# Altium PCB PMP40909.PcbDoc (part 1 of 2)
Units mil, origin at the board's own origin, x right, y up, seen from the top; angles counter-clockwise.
Board outline 3960.53 x 2185.03 mil, 4 copper layers (Top Layer, Signal Layer 1, Signal Layer 2, Bottom Layer), stack 45.434 mil thick; 68 components, 27 nets, 148 pads, 352 vias.
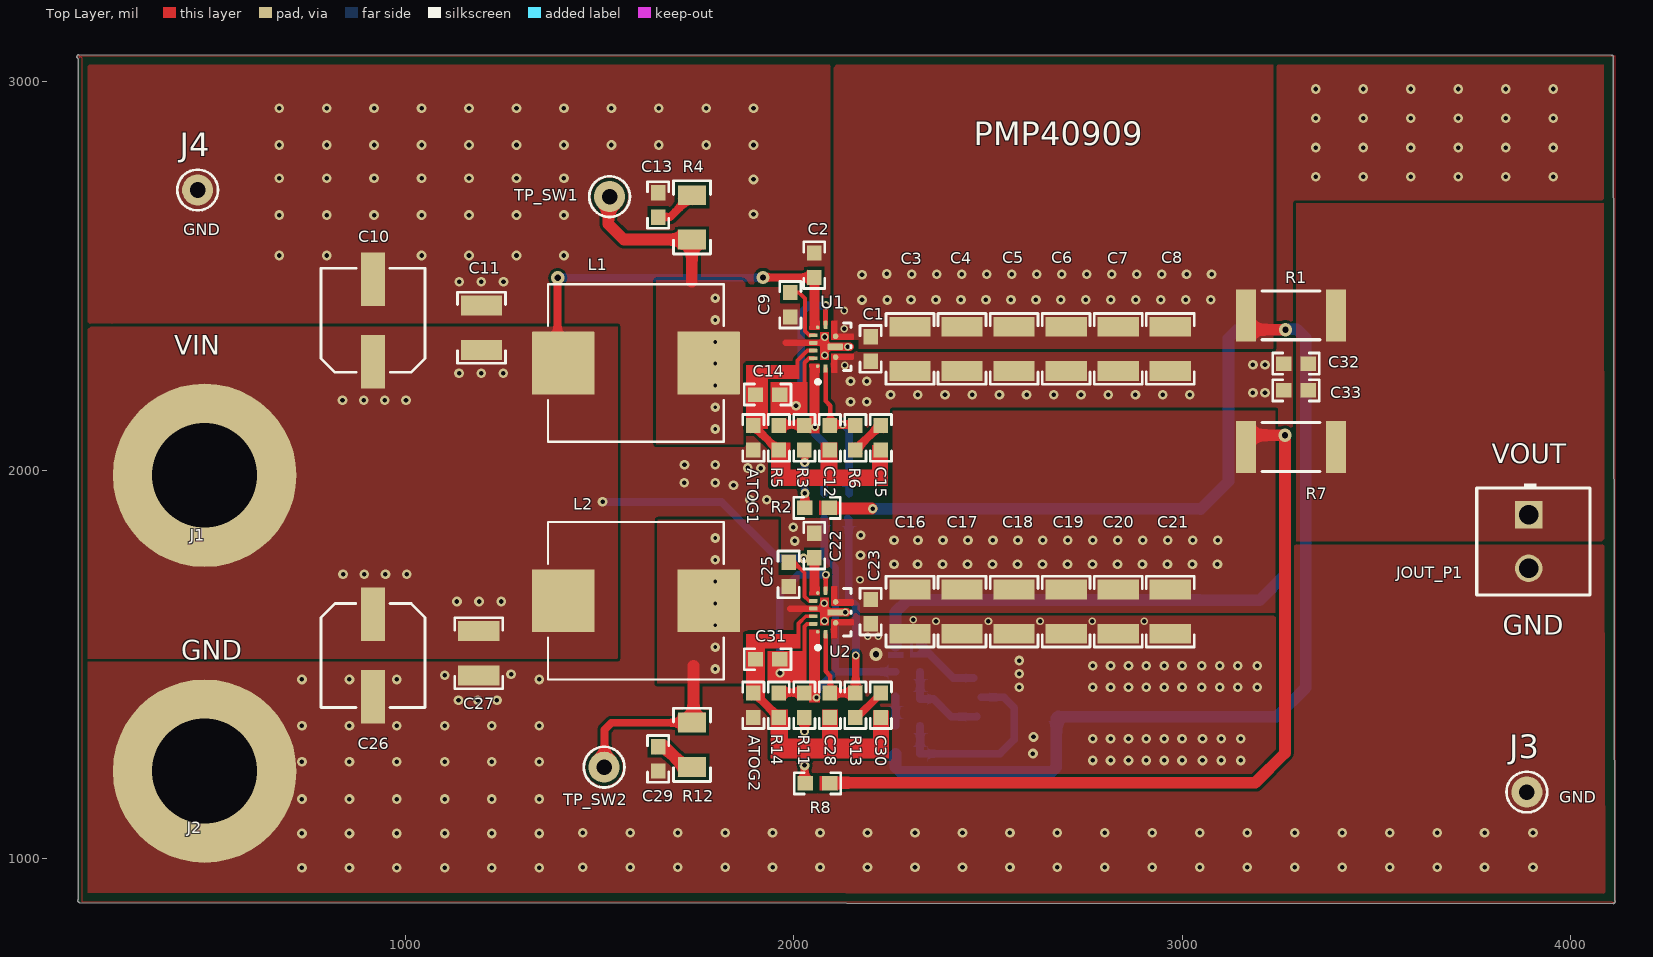
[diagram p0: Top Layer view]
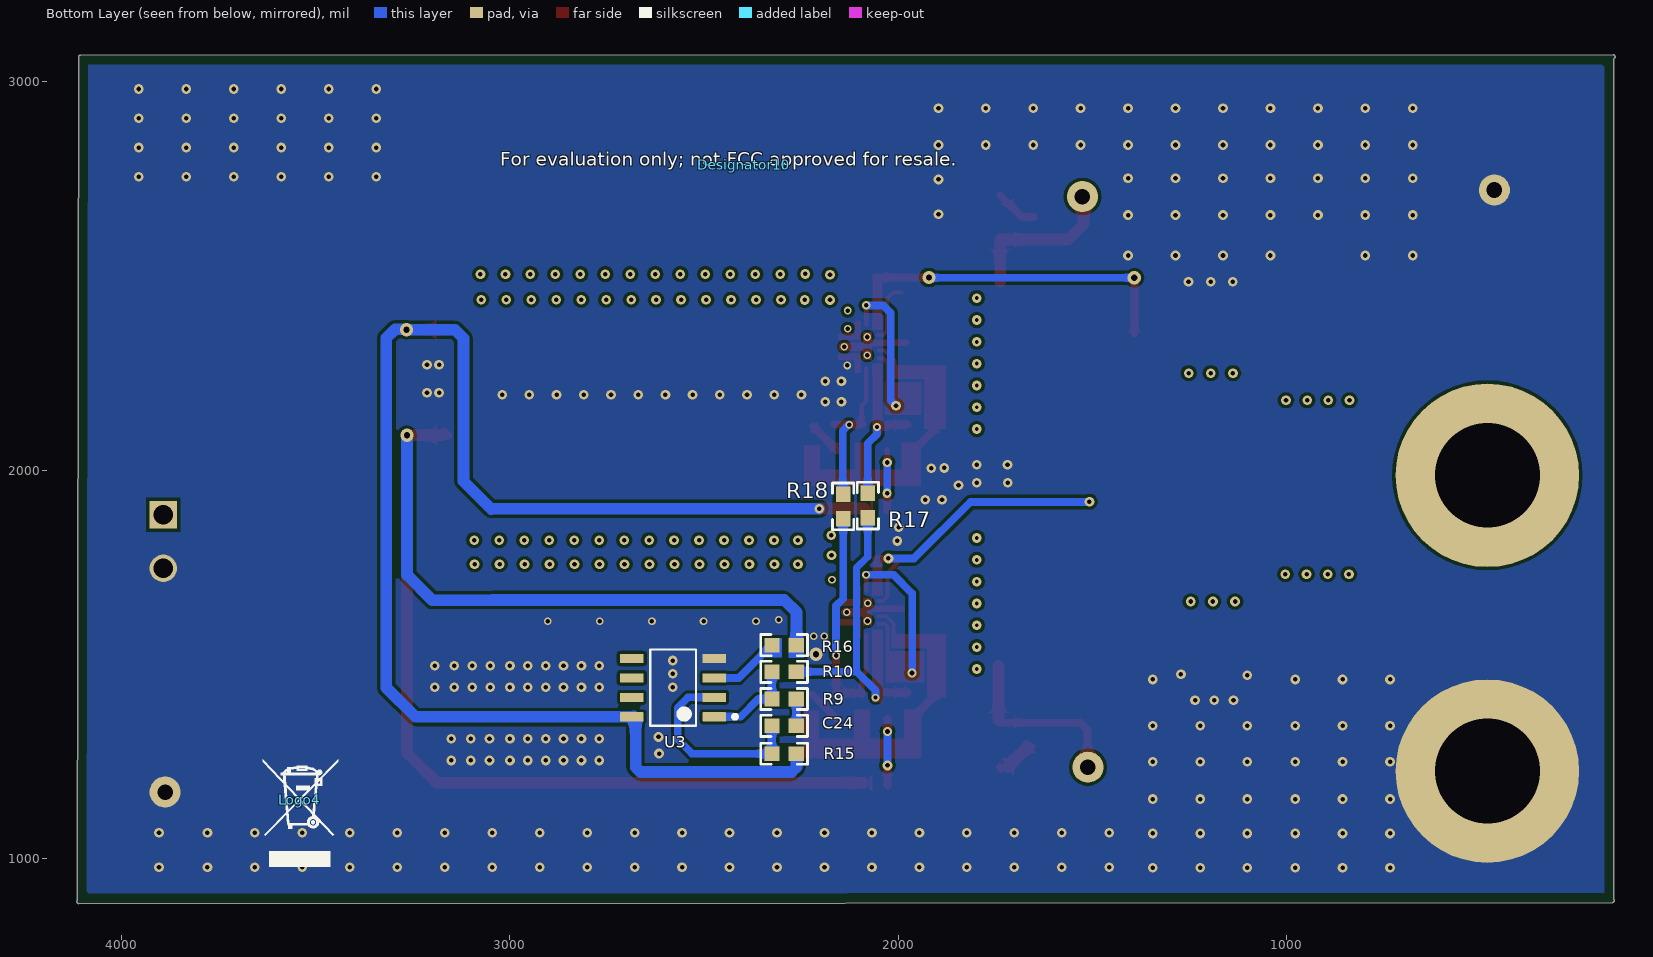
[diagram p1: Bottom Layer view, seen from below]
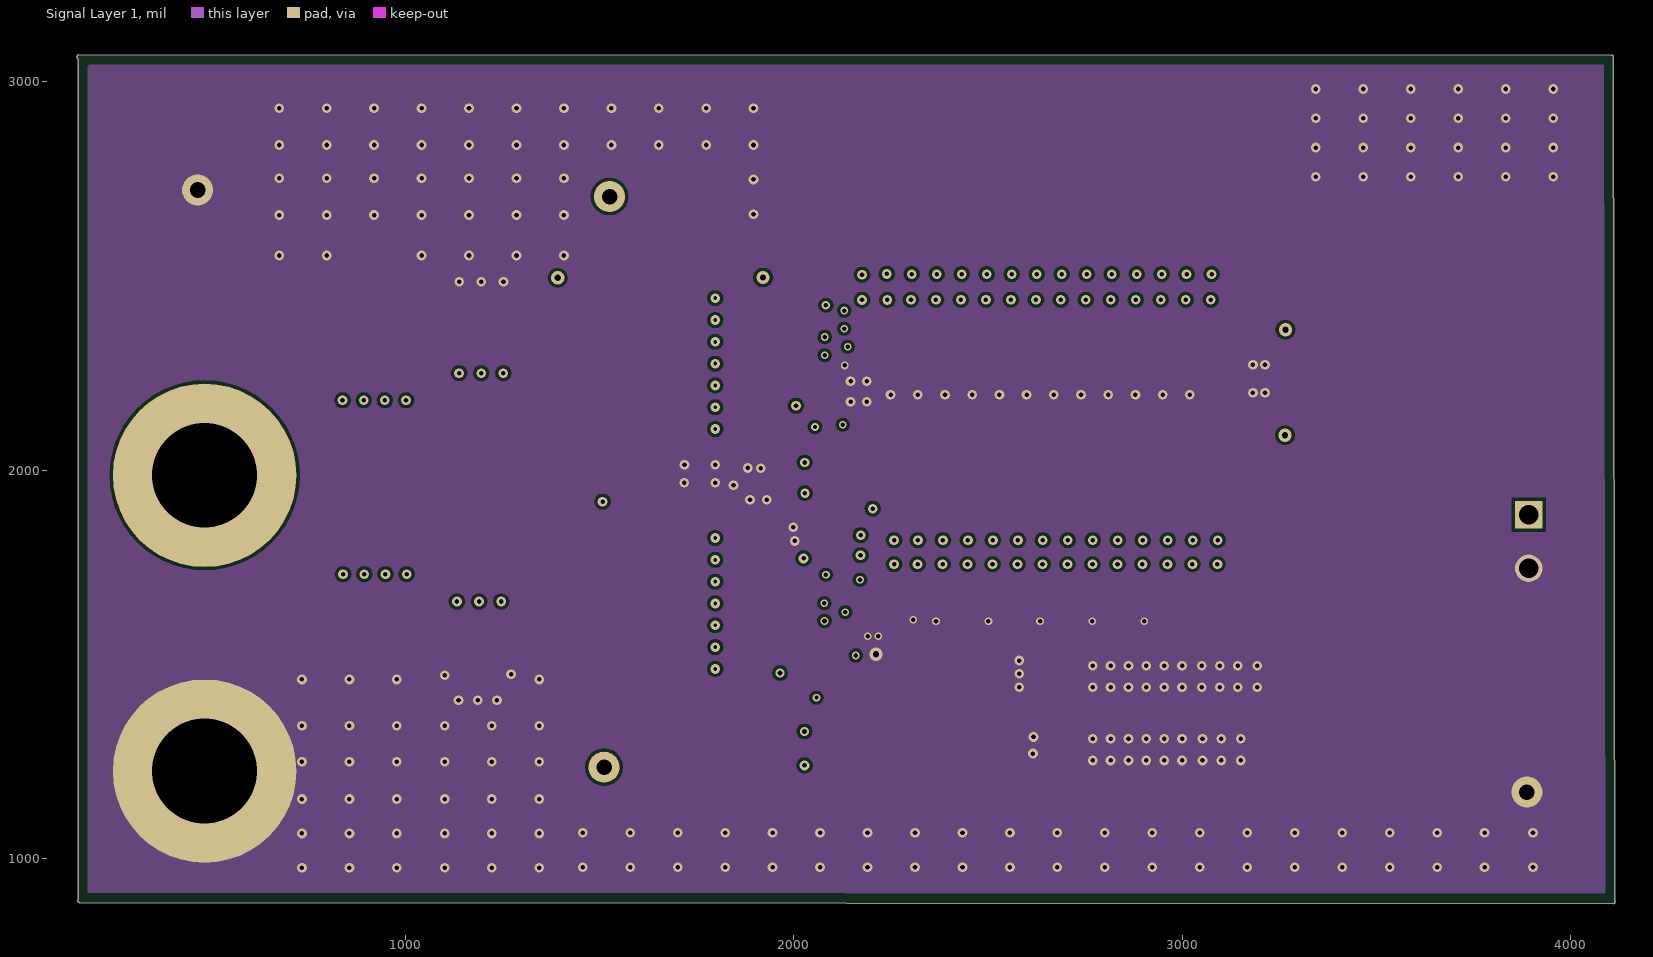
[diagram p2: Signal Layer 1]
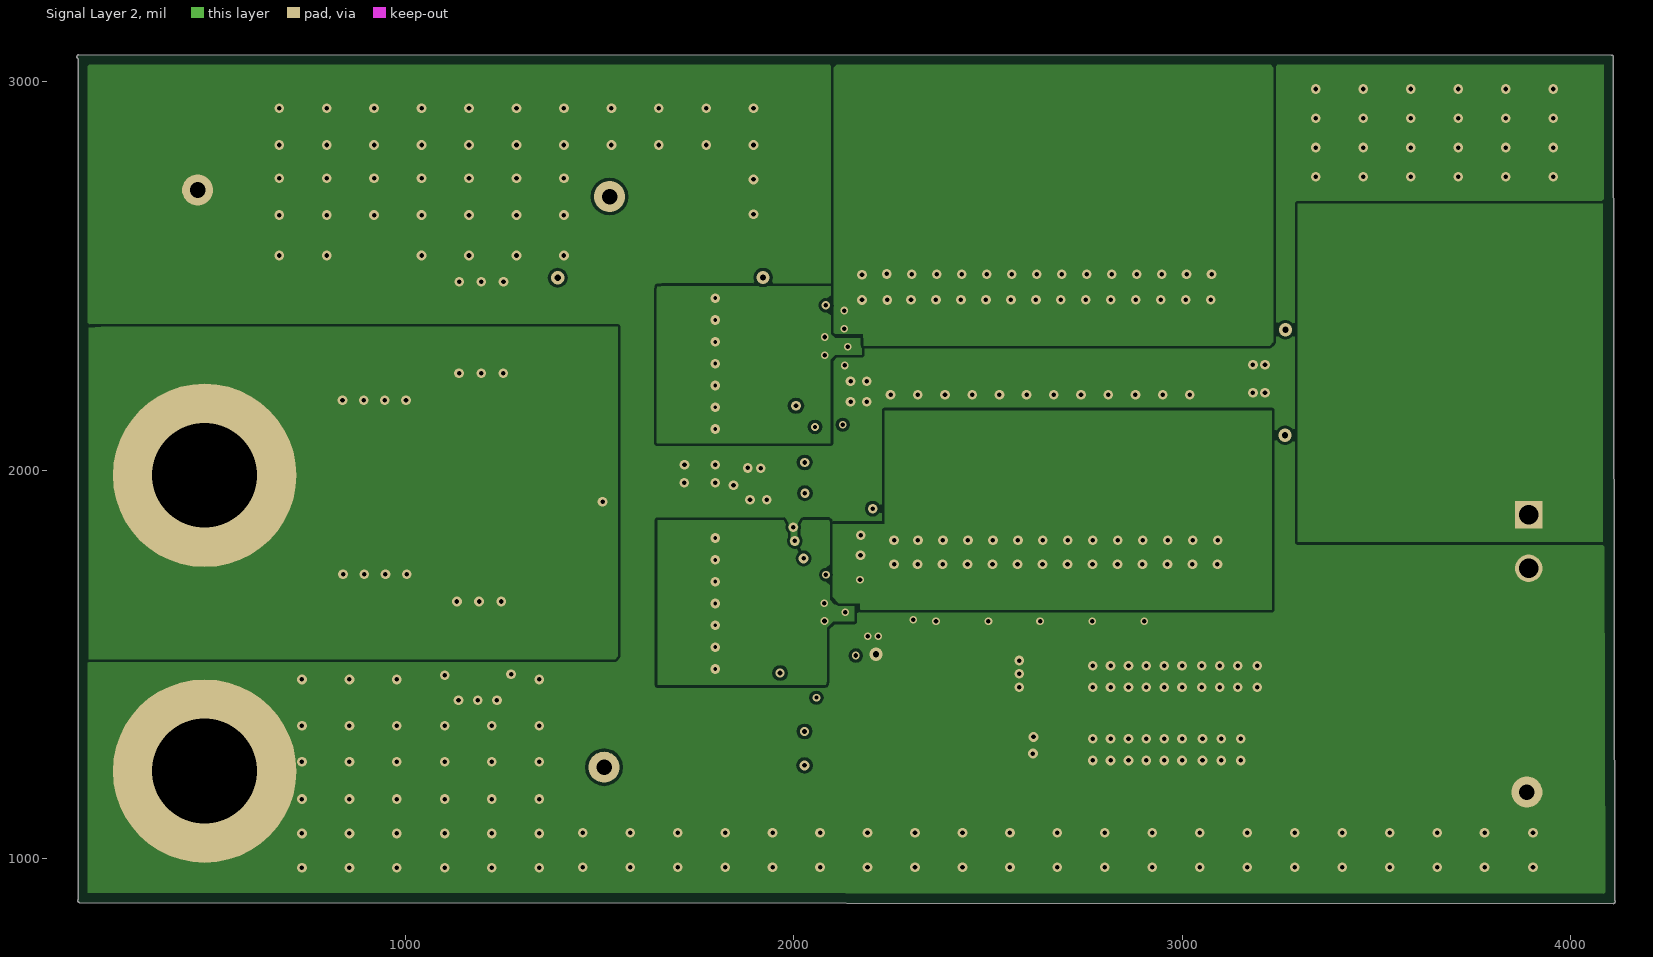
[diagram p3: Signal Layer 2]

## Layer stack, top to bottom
Top Solder: solder mask 0.4, Solder Resist, Dk 3.5
Top Layer: signal copper 2.8
Dielectric1: core 13, FR-4, Dk 4.8
Signal Layer 1: signal copper 1.417
Dielectric 2: core 11, FR-4, Dk 4.2
Signal Layer 2: signal copper 1.417
Dielectric 3: core 13, FR-4, Dk 4.2
Bottom Layer: signal copper 2.8
Bottom Solder: solder mask 0.4, Solder Resist, Dk 3.5

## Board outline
157.49,897 157.49,3059 cw(c162.5,3059) 157.56,3059.87 cw(c159.5,3064.5) 159.5,3069.52 4105.5,3069.02 cw(c4105.5,3064) 4110.52,3064 cw(c4105.5,3064) 4110.51,3063.75 cw(c4105.5,3063.5) 4110.52,3063.51 4114.34,892.02 cw(c4110,889.5) 4115.02,889.5 cw(c4110,889.5) 4110,884.49 162,886.99 cw(c162,892) 157.93,894.93 cw(c162.5,897)

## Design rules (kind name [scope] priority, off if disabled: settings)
AcuteAngle [All] p1: minimum=4.50000000000000E+0001 checktracksonly=FALSE
AssemblyTestPointUsage [All] p1: valid=2
BoardOutlineClearance BoardOutlineClearance_MountingHoles [OnCopper and InComponentClass('Mounting Holes')] p1: gap=39.37 ignorepadtopadclearanceinfootprint=FALSE
BoardOutlineClearance BoardOutlineClearance_Poly [OnCopper and IsPoly] p2: gap=25 ignorepadtopadclearanceinfootprint=FALSE
BoardOutlineClearance [OnCopper and Not InComponentClass('Logo') and not InComponentClass('FiducialMark') and not InRegion(1000,500,4000,800) and not InPoly] p3: gap=75 ignorepadtopadclearanceinfootprint=FALSE
Clearance Clearance_Keepouts [((IsTrack Or IsArc) And Not InPoly) And IsFree and IsKeepOut vs ((IsTrack Or IsArc) And Not InPoly) And IsFree and IsKeepOut] p1: gap=0 ignorepadtopadclearanceinfootprint=FALSE
Clearance Clearance_Poly [InPolygon] p2: gap=8 ignorepadtopadclearanceinfootprint=TRUE
Clearance Clearance_FiducialMark [IsKeepOut and InComponentClass('FiducialMark') vs IsPad and InComponentClass('FiducialMark')] p3: gap=0 ignorepadtopadclearanceinfootprint=FALSE
Clearance [All] p4: gap=6 ignorepadtopadclearanceinfootprint=TRUE
ComponentClearance ComponentClearance_MountingHoles_FiducialMarks [InComponentClass('Mounting Holes') vs InComponentClass('FiducialMark')] p1: gap=50 collisioncheckmode=3 verticalgap=10 showdistances=FALSE
ComponentClearance ComponentClearance_Shunt [InComponentClass('Header') vs InComponentClass('Shunt')] p2: gap=0 collisioncheckmode=3 verticalgap=0 showdistances=FALSE
ComponentClearance ComponentClearance_Logo [InComponentClass('Logo')] p3: gap=50 collisioncheckmode=3 verticalgap=10 showdistances=FALSE
ComponentClearance ComponentClearance_ScrewToNut [(HasFootprint('NY PMS 440 0025 PH')) vs (HasFootprint('Keystone_1902C'))] p4: gap=5 collisioncheckmode=3 verticalgap=10 showdistances=FALSE
ComponentClearance ComponentClearance_MountingHoles [InComponentClass('Mounting Holes')] p5: gap=250 collisioncheckmode=3 verticalgap=100000 showdistances=FALSE
ComponentClearance ComponentClearance_SmallPassives [HasFootprint('0201*') or HasFootprint('0402*') or HasFootprint('0508') or HasFootprint('0603*') or HasFootprint('0612') or HasFootprint('0805*') or HasFootprint('0815*') or HasFootprint('0830*') or HasFootprint('1206*') or HasFootprint('1210*') or HasFootprint('1808*') or HasFootprint('1812*') or HasFootprint('1825*') or HasFootprint('2010*') or HasFootprint('2220*') or HasFootprint('2225*') or HasFootprint('2512*') or HasFootprint('2728*') or HasFootprint('3518*') vs HasFootprint('0201*') or HasFootprint('0402*') or HasFootprint('0508') or HasFootprint('0603*') or HasFootprint('0612') or HasFootprint('0805*') or HasFootprint('0815*') or HasFootprint('0830*') or HasFootprint('1206*') or HasFootprint('1210*') or HasFootprint('1808*') or HasFootprint('1812*') or HasFootprint('1825*') or HasFootprint('2010*') or HasFootprint('2220*') or HasFootprint('2225*') or HasFootprint('2512*') or HasFootprint('2728*') or HasFootprint('3518*')] p6: gap=14.96 collisioncheckmode=3 verticalgap=10 showdistances=FALSE
ComponentClearance ComponentClearance_THtoSMT [IsThruComponent vs IsSMTComponent] p7: gap=40 collisioncheckmode=3 verticalgap=30 showdistances=FALSE
ComponentClearance ComponentClearance_THtoTH [IsThruComponent vs IsThruComponent] p8: gap=30 collisioncheckmode=3 verticalgap=30 showdistances=FALSE
ComponentClearance [All] p9: gap=30 collisioncheckmode=3 verticalgap=10 showdistances=FALSE
DiffPairsRouting [All] p1: maxlimit=100 minlimit=10 mostfreqgap=10 toplayer_minwidth=15 toplayer_maxwidth=15 toplayer_prefwidth=15 midlayer1_minwidth=15 midlayer1_maxwidth=15 midlayer1_prefwidth=15 midlayer2_minwidth=15 midlayer2_maxwidth=15 midlayer2_prefwidth=15 bottomlayer_minwidth=15 bottomlayer_maxwidth=15 bottomlayer_prefwidth=15 maxuncoupledlength=1000
FabricationTestPointUsage TestPointUsage [All] p1: valid=2 allowmultiple=FALSE
FabricationTestpoint Testpoint [All] p1: side=3 testpointundercomponent=TRUE minsize=40 maxsize=100 preferedsize=60 minholesize=0 maxholesize=40 preferedholesize=32 testpointgrid=1 allowsidetop=TRUE allowsidebottom=TRUE usegrid=TRUE gridtolerance=0.01
FanoutControl Fanout_LCC [IsLCC] p1: bgadir=Out bgaviamode=Centered fanoutstyle=Auto fanoutdirection=Alternating viagrid=1 // Fanout_LCC (Default Rule)
FanoutControl Fanout_BGA [IsBGA] p2: bgadir=Out bgaviamode=Centered fanoutstyle=Auto fanoutdirection=Alternating viagrid=1 // Fanout_BGA (Default Rule)
FanoutControl Fanout_Default [All] p4: bgadir=Out bgaviamode=Centered fanoutstyle=Auto fanoutdirection=Alternating viagrid=1 // Fanout_Default (Default Rule)
FanoutControl Fanout_Small [(CompPinCount < 5)] p5: bgadir=Out bgaviamode=Centered fanoutstyle=Auto fanoutdirection=OutThenIn viagrid=1 // Fanout_Small (Default Rule)
HoleSize [All] p1: absolutevalues=TRUE maxlimit=280 minlimit=7.87 maxpercent=80.000 minpercent=20.000
MinimumAnnularRing MinimumAnnularRing_ThermalPadVias [IsVia and InAnyComponent] p1: minimumring=0
MinimumAnnularRing [All] p2: minimumring=3
MinimumSolderMaskSliver MinimumSolderMaskSliver_Logo [InComponentClass('Logo') vs InComponentClass('Logo')] p1: minsoldermaskwidth=0.7
MinimumSolderMaskSliver [All] p2: minsoldermaskwidth=0
NetAntennae NetAntennae_1 [InNet('VOUT1') And OnLayer('Top Layer')] p1: netantennaetolerance=100
NetAntennae [InNet('VOUT2') And OnLayer('Top Layer')] p2: netantennaetolerance=100
PlaneClearance [All] p1: clearance=10
PlaneConnect [All] p1: planeconnectstyle=Direct reliefexpansion=10 reliefentries=4 reliefconductorwidth=10 reliefairgap=10
PolygonConnect PolygonConnect_1 [All vs IsNamedPolygon('SIGNAL_LAYER_2_VOUT1_P134') Or  IsNamedPolygon('TOP_LAYER_NONET_P000')] p1: connectstyle=Direct reliefconductorwidth=10 reliefentries=4 polygonreliefangle="90 Angle" airgapwidth=10
PolygonConnect [All] p2: connectstyle=Direct reliefconductorwidth=10 reliefentries=4 polygonreliefangle="90 Angle" airgapwidth=10
RoutingVias ThermalPadVias [IsVia and InAnyComponent] p1: holewidth=7.87 width=19.68 viastyle="Through Hole" minholewidth=4 minwidth=10 maxholewidth=12.99 maxwidth=23.62
RoutingVias [All] p2: holewidth=16 width=34 viastyle="Through Hole" minholewidth=4 minwidth=10 maxholewidth=40 maxwidth=65
SilkToBoardRegionClearance [Not ((IsComment or IsDesignator) And (Hide <> 'False')) and not InRegion(1000,500,4000,800)] p1:
SilkToSilkClearance SilkToSilkClearance_Pb-FreeLogo [(HasFootprint('Pb-Free_Overlay_Medium') OR HasFootprint('Pb-Free_Overlay_Small')) vs (HasFootprint('Pb-Free_Overlay_Medium') OR HasFootprint('Pb-Free_Overlay_Small'))] p1: silktosilkclearance=0
SilkToSilkClearance [All] p2: silktosilkclearance=0
SilkToSolderMaskClearance SilkToComponentPadClearance [(IsPad or IsFill or IsRegion) and InAnycomponent] p1: minsilkscreentomaskgap=0 clearancetoexposedcopper=TRUE
SilkToSolderMaskClearance "Silk to Solder Mask Opening" [All] p2: minsilkscreentomaskgap=0 clearancetoexposedcopper=FALSE
SolderMaskExpansion [All] p1: expansion=1.97 istentingtop=FALSE
UnRoutedNet [All] p1: checkbadconnections=TRUE
Width [All] p1: maxlimit=100 minlimit=6 preferedwidth=10 checkconnectedcopper=TRUE
12 further rules are at their usual default settings.

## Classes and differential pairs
component class Hardware: Logo3 Logo4

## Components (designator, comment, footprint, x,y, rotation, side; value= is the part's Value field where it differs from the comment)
ATOG1 "RMCF0603ZT0R00" 0603 1896.5,2083.5 r90 top value=0
ATOG2 "RMCF0603ZT0R00" 0603 1896.5,1395 r90 top value=0
C1 "GRT188R61H105ME13D" 0603 2198,2312.5 r270 top value=1uF
C2 "CGA3E2X7R1H104K080AA" 0603 2053,2528 r270 top value=0.1uF
C3 "GRM32ER71E226KE15L" 1210_270 2299.5,2312.5 r270 top value=22uF
C4 "GRM32ER71E226KE15L" 1210_270 2433.5,2312.5 r270 top value=22uF
C5 "GRM32ER71E226KE15L" 1210_270 2567.5,2312.5 r270 top value=22uF
C6 "GRM32ER71E226KE15L" 1210_270 2701.5,2312.5 r270 top value=22uF
C7 "GRM32ER71E226KE15L" 1210_270 2835.5,2312.5 r270 top value=22uF
C8 "GRM32ER71E226KE15L" 1210_270 2969.5,2312.5 r270 top value=22uF
C9 "CGA3E2X7R1H104K080AA" 0603 1991.5,2426 r90 top value=0.1uF
C10 "EEHZA1E101XP" SM_RADIAL_6.3BMM 917,2386 r90 top value=100uF
C11 "GRM32ER71E226KE15L" 1210_270 1196.5,2367 r90 top value=22uF
C12 "GRM1885C1H101JA01D" 0603 2093.23,2083.5 r270 top value=100pF
C13 "GRM188R72E222KW07D" 0603 1650.93,2683 r90 top value=2200pF
C14 "0603ZD475KAT2A" 0603 1933,2195 r0 top value=4.7uF
C15 "GRM188R71H102KA01D" 0603 2224.5,2083.5 r90 top value=1000pF
C16 "GRM32ER71E226KE15L" 1210_270 2299.5,1636 r90 top value=22uF
C17 "GRM32ER71E226KE15L" 1210_270 2433.5,1636 r90 top value=22uF
C18 "GRM32ER71E226KE15L" 1210_270 2567.5,1636 r90 top value=22uF
C19 "GRM32ER71E226KE15L" 1210_270 2701.5,1636 r90 top value=22uF
C20 "GRM32ER71E226KE15L" 1210_270 2835.5,1636 r90 top value=22uF
C21 "GRM32ER71E226KE15L" 1210_270 2969.5,1636 r90 top value=22uF
C22 "CGA3E2X7R1H104K080AA" 0603 2053,1806 r270 top value=0.1uF
C23 "GRT188R61H105ME13D" 0603 2198,1636 r270 top value=1uF
C24 "C0603X332K5RACTU" 0603 2294,1342.02 r0 bottom value=3300pF
C25 "CGA3E2X7R1H104K080AA" 0603 1987,1732 r90 top value=0.1uF
C26 "EEHZA1E101XP" SM_RADIAL_6.3BMM 917,1523 r270 top value=100uF
C27 "GRM32ER71E226KE15L" 1210_270 1189,1529 r270 top value=22uF
C28 "GRM1885C1H101JA01D" 0603 2093.23,1395 r270 top value=100pF
C29 "GRM188R72E222KW07D" 0603 1651,1257 r270 top value=2200pF
C30 "GRM188R71H102KA01D" 0603 2224.5,1395 r90 top value=1000pF
C31 "0603ZD475KAT2A" 0603 1933,1513.5 r0 top value=4.7uF
C32 "GRT188R61H105ME13D" 0603 3293.33,2274.5 r180 top value=1uF
C33 "GRT188R61H105ME13D" 0603 3293.33,2205.5 r180 top value=1uF
Designator10 "Comment" FCC_disclaimer 2397.5,2786 r180 bottom
J1 "108-0740-001" Johnson_108-0740-001 483.5,1987 r90 top
J2 "108-0740-001" Johnson_108-0740-001 483.5,1225.5 r90 top
J3 "5003" Keystone5003 3887.69,1171.5 r0 top
J4 "5003" Keystone5003 465.5,2721.5 r0 top
JOUT_P1 "691214110002" Wurth_691214110002 3892.5,1816.5 r270 top
L1 "CMLE105T-2R2MS-99" FP-CMLE105T-2R2MS-99_SMT_IND_11MM15_10MM0-MFG 1594,2276 r0 top
L2 "CMLE105T-2R2MS-99" FP-CMLE105T-2R2MS-99_SMT_IND_11MM15_10MM0-MFG 1594,1664 r0 top
Logo3 "FCC disclaimer" FCC_disclaimer 2350,3380 r0 top
Logo4 "WEEE logo" WEEE_Minimum 3541,1152 r180 bottom
R1 "WSL2512R0100FEA" 2512 3280.28,2399 r0 top value=0.01
R2 "ERJ-3EKF49R9V" 0603 2060,1903 r0 top value=49.9
R3 "CRCW0603165KFKEA" 0603 2027.7,2083.5 r90 top value=165k
R4 "CRCW12061R20FKEA" 1206 1738,2651 r90 top value=1.20
R5 "RCG060310K0FKEA" 0603 1962.03,2083.5 r270 top value=10.0k
R6 "RG1608P-303-B-T5" 0603 2158.83,2083.5 r270 top value=30.0k
R7 "WSL2512R0100FEA" 2512 3280.28,2060 r0 top value=0.01
R8 "ERJ-3EKF49R9V" 0603 2061.5,1194 r180 top value=49.9
R9 "RCG060310K0FKEA" 0603 2294,1411.09 r0 bottom value=10.0k
R10 "CRCW06031M30FKEA" 0603 2294,1481 r180 bottom value=1.30Meg
R11 "CRCW0603165KFKEA" 0603 2027.7,1395 r90 top value=165k
R12 "CRCW12061R20FKEA" 1206 1738,1293 r270 top value=1.20
R13 "RG1608P-303-B-T5" 0603 2158.83,1395 r270 top value=30.0k
R14 "RCG060310K0FKEA" 0603 1961.5,1395 r270 top value=10.0k
R15 "ERJ-3EKF1000V" 0603 2294,1270 r0 bottom value=100
R16 "ERJ-3EKF1000V" 0603 2294,1550 r0 bottom value=100
R17 "RMCF0603ZT0R00" 0603 2078.5,1909 r90 bottom value=0
R18 "RMCF0603ZT0R00" 0603 2142,1907 r90 bottom value=0
TP_SW1 "5003" Keystone5003 1526.03,2704.51 r90 top
TP_SW2 "5003" Keystone5003 1512,1235.49 r180 top
U1 "TPS61288RQQR" RQQ0011A-MFG 2097,2318 r90 top
U2 "TPS61288RQQR" RQQ0011A-MFG 2097,1634 r90 top
U3 "TLV9152IDR" D0008A-MFG 2580,1440.3 r0 bottom

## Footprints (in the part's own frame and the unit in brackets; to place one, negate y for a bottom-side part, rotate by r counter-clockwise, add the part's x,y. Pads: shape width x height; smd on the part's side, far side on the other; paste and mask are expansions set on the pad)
0603 [mm] "0603 from SM-752 data"
  rect 1x0.95 smd: 1(-0.8,0) 2(0.8,0)
  silkscreen extent -1.52,-0.69 1.52,0.69, body extent -0.87,-0.47 0.87,0.47, height 1
1206 [mm] "1206 from SM-752 data"
  rect 1.3x1.85 smd: 1(-1.45,0) 2(1.45,0)
  silkscreen extent -2.4,-1.21 2.4,1.21, body extent -1.7,-0.9 1.7,0.9, height 1.35
1210_270 [mm] "1210"
  rect 1.3x2.7 smd: 1(-1.45,0) 2(1.45,0)
  silkscreen extent -2.32,-1.57 2.32,1.57, body extent -1.7,-1.35 1.7,1.35, height 2.7
2512 [mm] "Chip Resistor, Body 6.3x3.2mm, IPC Medium Density"
  rect 1.3x3.4 smd: 1(-2.95,0) 2(2.95,0)
  silkscreen extent -1.9,-1.6 1.9,1.6, body extent -3.22,-1.67 3.22,1.67, height 0.71
D0008A-MFG [mm]
  rrect17% 1.55x0.6 smd paste+0 mask+0: 1(-2.7,1.905) 2(-2.7,0.635) 3(-2.7,-0.635) 4(-2.7,-1.905) 5(2.7,-1.905) 6(2.7,-0.635) 7(2.7,0.635) 8(2.7,1.905)
  silkscreen extent -4.17,-2.5 1.5,2.5, body extent -3,-2.45 3,2.45, height 1.75
FCC_disclaimer [mil]
FP-CMLE105T-2R2MS-99_SMT_IND_11MM15_10MM0-MFG [mm]
  rrect2% 4.1x4.1 smd paste+0 mask+0: 1(-4.75,0) 2(4.75,0)
  silkscreen extent -5.75,-5.15 5.75,5.15, body extent -6.9,-5.25 6.9,5.25, height 0.25
Johnson_108-0740-001 [mm] "Banana Jack Uninsulated Standard Type"
  round 12 hole 6.858: 1(0,0)
  body extent -4.77,-5.43 4.75,5.57, height 2.39
Keystone5003 [mil] "For Keystone 500x miniature loop terminals"
  round 80 hole 40: 1(0,0)
  silkscreen extent -52,-52 52,52, body extent -49,-49 49,49, height 182
RQQ0011A-MFG [mm]
  round 0.241 smd paste+0 mask+0: 1(-1.269,0.894) 7(1.269,0.894)
  rrect40% 0.55x0.25 smd paste+0 mask+0: 2(-1.425,0.375) 6(1.425,0.375)
  round 0.37 smd paste-1000 mask+0: 3(-0.684,-0.278) 5(0.684,-0.278)
  rrect25% 0.4x1 smd paste+0 mask+0: 4(0,-0.25)
  rrect40% 0.25x0.55 smd paste+0 mask+0: 8(0.75,1.175) 9(0.25,1.175) 10(-0.25,1.175) 11(-0.75,1.175)
  Top Layer region: -0.85,-0.4 -0.85,-1.4 -0.843,-1.425 -0.825,-1.443 -0.8,-1.45 -0.8,-1.45 -0.5,-1.45 -0.481,-1.446 -0.465,-1.435 -0.454,-1.419 -0.45,-1.4 -0.45,-1.4 -0.45,-0.05 -0.454,-0.031 -0.465,-0.015 -0.481,-0.004 -0.5,0 -0.5,0 -1.65,0 -1.669,-0.004 -1.685,-0.015 -1.696,-0.031 -1.7,-0.05 -1.7,-0.05 -1.7,-0.35 -1.693,-0.375 -1.675,-0.393 -1.65,-0.4 -1.65,-0.4
  Top Layer region: 0.85,-0.4 0.85,-1.4 0.843,-1.425 0.825,-1.443 0.8,-1.45 0.8,-1.45 0.5,-1.45 0.481,-1.446 0.465,-1.435 0.454,-1.419 0.45,-1.4 0.45,-1.4 0.45,-0.05 0.454,-0.031 0.465,-0.015 0.481,-0.004 0.5,0 0.5,0 1.65,0 1.669,-0.004 1.685,-0.015 1.696,-0.031 1.7,-0.05 1.7,-0.05 1.7,-0.35 1.693,-0.375 1.675,-0.393 1.65,-0.4 1.65,-0.4
  Top Layer region: -1.35,1 -1.65,1 -1.669,0.996 -1.685,0.985 -1.696,0.969 -1.7,0.95 -1.7,0.95 -1.7,0.8 -1.696,0.781 -1.685,0.765 -1.669,0.754 -1.65,0.75 -1.65,0.75 -1.175,0.75 -1.156,0.754 -1.14,0.765 -1.129,0.781 -1.125,0.8 -1.125,0.8 -1.125,1.4 -1.129,1.419 -1.14,1.435 -1.156,1.446 -1.175,1.45 -1.175,1.45 -1.3,1.45 -1.319,1.446 -1.335,1.435 -1.346,1.419 -1.35,1.4 -1.35,1.4
  Top Layer region: 1.35,1 1.65,1 1.675,0.993 1.693,0.975 1.7,0.95 1.7,0.95 1.7,0.8 1.696,0.781 1.685,0.765 1.669,0.754 1.65,0.75 1.65,0.75 1.175,0.75 1.156,0.754 1.14,0.765 1.129,0.781 1.125,0.8 1.125,0.8 1.125,1.4 1.129,1.419 1.14,1.435 1.156,1.446 1.175,1.45 1.175,1.45 1.3,1.45 1.325,1.443 1.343,1.425 1.35,1.4 1.35,1.4
  silkscreen extent -2.42,-1.3 1.55,1, body extent -1.8,-1.55 1.8,1.55, height 0.25
SM_RADIAL_6.3BMM [mm] "Nichicon 6.3x7.7"
  rect 3.5x1.6 smd: 1(-2.7,0) 2(2.7,0)
  silkscreen extent -3.4,-3.4 3.4,3.4, body extent -3.4,-3.4 3.4,3.4, height 8
WEEE_Minimum [mil] "WEEElie bin"
  silkscreen extent -95,-172 99,104
Wurth_691214110002 [mm] "Receptacle, 3.5mm, 2x1, TH"
  rect 1.8x1.8 hole 1.3: 1(-1.75,0)
  round 1.8 hole 1.3: 2(1.75,0)
  silkscreen extent -3.8,-3.4 3.5,4, body extent -3.9,-3.4 3.5,4, height 8.5

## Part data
ATOG1 ATOG2 R17 R18: library part CMP-0023343-2, "RES, 0, 1%, 0.1 W, AEC-Q200 Grade 0, 0603", Manufacturer="Stackpole Electronics Inc", Power_W=100mW, Supplier Part Number 1=RMCF0603ZT0R00CT-ND, TempCo=ppm/C, Tolerance_%=1%, Value2=0.1W, Value_Code=0
C1 C23 C32 C33: library part CMP-0081784-1, "CAP, CERM, 1 µF, 50 V,+/- 20%, X5R, AEC-Q200 Grade 3, 0603", Cap_Case=0603, Manufacturer=MuRata, Supplier Part Number 1=490-12331-1-ND, TempCo=X5R, Tolerance_%=20%, Value2=50V, ValueDisplayed=1µF
C2 C9 C22 C25: library part CMP-0007078-2, "CAP, CERM, 0.1 uF, 50 V, +/- 10%, X7R, AEC-Q200 Grade 1, 0603", Cap_Case=0603, Manufacturer=TDK, Supplier Part Number 1=445-5666-1-ND, TempCo=X7R, Tolerance_%=10%, Value1="0.0296 ohm", Value2=50V, ValueDisplayed=0.1uF
C3 C4 C5 C6 C7 C8 C11 C16 C17 C18 C19 C20 C21 C27: library part CMP-0009224-2, "CAP, CERM, 22 uF, 25 V, +/- 10%, X7R, 1210", Cap_Case=1210, Manufacturer=MuRata, Supplier Part Number 1=490-5313-1-ND, TempCo=X7R, Tolerance_%=10%, Value1=Unknown, Value2=25V, ValueDisplayed=22uF
C10 C26: library part CMP-0012570-3, "CAP, Polymer Hybrid, 100 uF, 25 V, +/- 20%, 30 ohm, 6.3x7.7 SMD", Manufacturer=Panasonic, Supplier Part Number 1=P15436CT-ND, Tolerance_%=20%, Value1="30 ohm", Value2=25V, ValueDisplayed=100uF
C12 C28: library part CMP-0007171-2, "CAP, CERM, 100 pF, 50 V, +/- 5%, C0G/NP0, 0603", Cap_Case=0603, Manufacturer=MuRata, Supplier Part Number 1=490-1427-1-ND, TempCo=C0G/NP0, Tolerance_%=5%, Value1=Unknown, Value2=50V, ValueDisplayed=100pF
C13 C29: library part CMP-0007493-2, "CAP, CERM, 2200 pF, 250 V, +/- 10%, X7R, 0603", Cap_Case=0603, Manufacturer=MuRata, Supplier Part Number 1=490-3530-1-ND, TempCo=X7R, Tolerance_%=10%, Value1=Unknown, Value2=250V, ValueDisplayed=2200pF
C14 C31: library part CMP-0006816-5, "CAP, CERM, 4.7 uF, 10 V, +/- 10%, X5R, 0603", Cap_Case=0603, Manufacturer=AVX, Supplier Part Number 1=478-7943-1-ND, TempCo=X5R, Tolerance_%=10%, Value1=Unknown, Value2=10V, ValueDisplayed=4.7uF
C15 C30: library part CMP-0007432-2, "CAP, CERM, 1000 pF, 50 V, +/- 10%, X7R, 0603", Cap_Case=0603, Manufacturer=MuRata, Supplier Part Number 1=490-1494-1-ND, TempCo=X7R, Tolerance_%=10%, Value1=Unknown, Value2=50V, ValueDisplayed=1000pF
C24: library part CMP-0006985-2, "CAP, CERM, 3300 pF, 50 V, +/- 10%, X7R, 0603", Cap_Case=0603, Manufacturer=Kemet, Supplier Part Number 1=399-5339-1-ND, TempCo=X7R, Tolerance_%=10%, Value1=Unknown, Value2=50V, ValueDisplayed=3300pF
J1 J2: library part CMP-0055387-2, "Standard Banana Jack, Uninsulated, 15A", Manufacturer="Cinch Connectivity", Supplier Part Number 1=J147-ND
J3 J4 TP_SW1 TP_SW2: library part CMP-0055140-1, "Test Point, Miniature, Orange, TH", Color=Orange, Manufacturer=Keystone, Supplier Part Number 1=36-5003-ND
JOUT_P1: library part CMP-0054825-2, "Terminal Block, 3.5mm, 2x1, Tin, TH", Color=Green, Current_A=10A, Manufacturer="Wurth Elektronik", Supplier Part Number 1=732-2747-ND, Voltage_V=300V
L1 L2: library part CMP-0089717-1, "Fixed Inductor 2.2uH 20% 100kHz 19.5A 4.5mOhm", Manufacturer=Cyntec, Operating Temperature Range="-55°C to +125°C", Test Frequency=100kHz, Tolerance_%=20%
Logo3: library part CMP-0074847-1, "FCC_disclaimer"
Logo4: library part CMP-0074769-1
R1 R7: library part CMP-0015850-2, "RES, 0.01, 1%, 1 W, 2512", Manufacturer=Vishay-Dale, Power_W=1W, Supplier Part Number 1=WSLG-.01CT-ND, TempCo="75 ppm/C", Tolerance_%=1%, Value_Code=R010, ValueDisplayed=0.01
R2 R8: library part CMP-0022707-2, "RES, 49.9, 1%, 0.1 W, AEC-Q200 Grade 0, 0603", Manufacturer=Panasonic, Power_W=100mW, Supplier Part Number 1=P49.9HCT-ND, TempCo="100 ppm/C", Tolerance_%=1%, Value2=0.1W, Value_Code=49R9, ValueDisplayed=49.9
R3 R11: library part CMP-0022075-2, "RES, 165 k, 1%, 0.1 W, 0603", Manufacturer=Vishay-Dale, Power_W=100mW, Supplier Part Number 1=541-165KHCT-ND, TempCo="100 ppm/C", Tolerance_%=1%, Value2=0.1W, Value_Code=165k
R4 R12: library part CMP-0016753-2, "RES, 1.20, 1%, 0.25 W, AEC-Q200 Grade 0, 1206", Manufacturer=Vishay-Dale, Power_W=250mW, Supplier Part Number 1=541-1.20FFCT-ND, TempCo="100 ppm/C", Tolerance_%=1%, Value2=0.25W, Value_Code=1R20, ValueDisplayed=1.20
R5 R9 R14: library part CMP-0023337-2, "RES, 10.0 k, 1%, 0.1 W, 0603", Manufacturer="Vishay Draloric", Power_W=100mW, Supplier Part Number 1=541-1784-1-ND, TempCo="100 ppm/C", Tolerance_%=1%, Value2=0.1W, Value_Code=10k0, ValueDisplayed=10.0k
R6 R13: library part CMP-0023508-2, "RES, 30.0 k, 0.1%, 0.1 W, 0603", Manufacturer="Susumu Co Ltd", Power_W=100mW, Supplier Part Number 1=RG16P30.0KBCT-ND, TempCo="25 ppm/C", Tolerance_%=0.1%, Value2=0.1W, Value_Code=30k0, ValueDisplayed=30.0k
R10: library part CMP-0022150-2, "RES, 1.30 M, 1%, 0.1 W, 0603", Manufacturer=Vishay-Dale, Power_W=100mW, Supplier Part Number 1=541-1.30MHCT-ND, TempCo="100 ppm/C", Tolerance_%=1%, Value2=0.1W, Value_Code=1M30, ValueDisplayed=1.30M
R15 R16: library part CMP-0022679-2, "RES, 100, 1%, 0.1 W, AEC-Q200 Grade 0, 0603", Manufacturer=Panasonic, Power_W=100mW, Supplier Part Number 1=P100HCT-ND, TempCo="100 ppm/C", Tolerance_%=1%, Value2=0.1W, Value_Code=100R, ValueDisplayed=100
U1 U2: library part CMP-0089018-1, "Fully Integrated Synchronous Boost Converter", Manufacturer="Texas Instruments", Operating Temperature Range="-40°C to +125°C"
U3: library part CMP-0091916-1, "General Purpose Amplifier 2 Circuit Rail-to-Rail 8-SOIC", Digikey Part Number=296-TLV9152IDRCT-ND, Input Bias Current=0.00001uA, Input Offset Voltage=0.125mV, Manufacturer="Texas Instruments", Max Dual Supply Voltage=8V, Max Supply Voltage=16V, Min Dual Supply Voltage=1.35V, Min Supply Voltage=2.7V, Mouser Part Number=595-TLV9152IDR, Nominal Supply Current=30-560uA, Operating Temperature Range="-40°C to +125°C", Output Current Per Channel=75mA

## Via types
v1: diameter 25, hole 11.81, Top Layer to Bottom Layer, tented both sides, 205 vias
v2: diameter 25, hole 11.81, Top Layer to Bottom Layer, 100 vias
v3: diameter 20, hole 11.81, Top Layer to Bottom Layer, tented both sides, 14 vias
v4: diameter 25, hole 10, Top Layer to Bottom Layer, 14 vias
v5: diameter 20, hole 11.81, Top Layer to Bottom Layer, 4 vias
v6: diameter 23.62, hole 11.81, Top Layer to Bottom Layer, tented both sides, 3 vias
v7: diameter 34, hole 16, Top Layer to Bottom Layer, tented both sides, 3 vias
v8: diameter 34, hole 16, Top Layer to Bottom Layer, 2 vias
v9: diameter 19.68, hole 11.81, Top Layer to Bottom Layer, tented both sides, 2 vias
v10: diameter 23.62, hole 13.78, Top Layer to Bottom Layer, tented both sides, 1 vias
v11: diameter 20, hole 10, Top Layer to Bottom Layer, tented both sides, 1 vias
v12: diameter 20, hole 10, Top Layer to Bottom Layer, 1 vias
v13: diameter 19.68, hole 11.81, Top Layer to Bottom Layer, 1 vias
v14: diameter 22, hole 11.81, Top Layer to Bottom Layer, tented both sides, 1 vias

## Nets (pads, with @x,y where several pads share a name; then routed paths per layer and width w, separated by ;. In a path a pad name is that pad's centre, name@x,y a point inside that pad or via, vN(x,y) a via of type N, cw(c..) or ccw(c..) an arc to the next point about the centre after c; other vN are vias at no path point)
AGND1: ATOG1.2 C12.2 C14.1 C15.1 R5.2 U1.10 | length 165.1
  Top Layer w10: 2010,2264 2010,2282.24 2035.92,2308.16 U1.10@2050.74,2308.16
  Top Layer w20: ATOG1.2@1896.5,2115 1961.5,2050 R5.2@1961.5,2046.5
AGND2: ATOG2.2 C28.2 C30.1 C31.1 R14.2 U2.10 | length 187.5
  Top Layer w10: ATOG2.2@1912,1435.7 1918.3,1435.7 ; R14.2@1963.5,1352.5 R14.2@1963.5,1362 ; 2012,1572 2012,1605 2031.16,1624.16 U2.10@2050.74,1624.16
  Top Layer w20: ATOG2.2@1896.5,1422.5 1903,1422.5 R14.2@1963.5,1362
COMP1: C12.1 R6.1 R18.2 U1.2 | length 424.4
  Top Layer w10: 2082,2247 2082,2261.66 U1.2@2082.24,2261.9 ; 2136.62,2117.62 2137,2118
  Top Layer w12: U1.2@2082.24,2261.9 2082.24,2178.26 2094.5,2166 C12.1@2094.5,2117.5
  Top Layer w20: C12.1@2091.5,2119 2093,2117.5 2094.5,2117.5 v13(2126.5,2117.5) 2163.5,2117.5 R6.1@2164.5,2118.5
  Bottom Layer w20: v13(2126.5,2117.5) 2127,2118 2143,2102 R18.2@2143,1940
COMP2: C28.1 R13.1 R18.1 U2.2 | length 688
  Top Layer w12: U2.2@2082.24,1577.9 2082.24,1482.38 2094.5,1470.11 2094.5,1425 C28.1@2094.5,1423.5
  Top Layer w20: C28.1@2093.5,1424 2094.5,1425 2095.5,1426 2160,1426 v9(2160,1523) ; R13.1@2160,1423.5 R13.1@2161.5,1422
  Bottom Layer w20: R18.1@2139,1876 2142,1873 2142,1669.5 2160.5,1651 2160.5,1523.5 v9(2160,1523)
FB1: R3.2 R5.1 R17.2 U1.1 | length 258.3
  Top Layer w20: R5.1@1976,2117.62 R3.2@2027.7,2117.62 ; R3.2@2030,2112.5 2031,2111.5 v12(2055,2111.5)
  Bottom Layer w20: v12(2055,2111.5) 2055,2093 2078.5,2069.5 R17.2@2078.5,1940.5 R17.2@2078.5,1940
FB2: R10.2 R11.2 R14.1 R17.1 U2.1 | length 731.4
  Top Layer w15: R11.2@2038,1427 2054,1443
  Top Layer w20: R14.1@1976,1427.83 2030.83,1427.83 R11.2@2033,1430
  Bottom Layer w15: 2109,1481.5 2109.5,1481
  Bottom Layer w18: 2078.5,1778 2107.5,1749 2107.5,1741.86 2108,1741.36 ; 2106.5,1484.5 2108,1486 2108,1644.86 ; 2107.5,1749.5 2108,1749 2108,1741.36 ; 2108,1646.86 2108,1741.36
  Bottom Layer w20: v11(2058.5,1414.5) 2058.5,1433 2105.5,1480 ; 2078.5,1778 R17.1@2078.5,1877.5 ; 2109.5,1481 2143.66,1481 R10.2@2262.5,1481
GND: ATOG1.1 ATOG2.1 C1.2 C2.1 C3.2 C4.2 C5.2 C6.2 C7.2 C8.2 C10.2 C11.2 C13.2 C16.1 C17.1 C18.1 C19.1 C20.1 C21.1 C22.1 C23.2 C26.2 C27.2 C29.2 C32.2 C33.2 J2.1 J3.1 J4.1 JOUT_P1.2 U1.3 U2.3 U3.4
  other v1: 734,976.5 856.21,976.5 978.41,976.5 1102,976.5 1222.82,976.5 1345.03,976.5 1456.94,978 1579.15,978 1701.35,978 1823.56,978 1945.76,978 2067.97,978 2190.18,978 2312.38,978 2434.59,978 2556.79,978 2679,978 2801.2,978 2923.41,978 3045.62,978 3167.82,978 3290.03,978 3412.23,978 3534.44,978 3656.65,978 3778.85,978 3903.56,978 734,1065 856.21,1065 978.41,1065 1102,1065 1222.82,1065 1345.03,1065 1456.94,1066.5 1579.15,1066.5 1701.35,1066.5 1823.56,1066.5 1945.76,1066.5 2067.97,1066.5 2190.18,1066.5 2312.38,1066.5 2434.59,1066.5 2556.79,1066.5 2679,1066.5 2801.2,1066.5 2923.41,1066.5 3045.62,1066.5 3167.82,1066.5 3290.03,1066.5 3412.23,1066.5 3534.44,1066.5 3656.65,1066.5 3778.85,1066.5 3903.56,1066.5 734,1153.5 856.21,1153.5 978.41,1153.5 1102,1153.5 1222.82,1153.5 1345.03,1153.5 734,1249.5 856.21,1249.5 978.41,1249.5 1102,1249.5 1222.82,1249.5 1345.03,1249.5 2770,1253 2816,1253 2862,1253 2908,1253 2954,1253 3000,1253 3052.5,1253 3101,1253 3151,1253 2616,1270.5 2770,1309 2816,1309 2862,1309 2908,1309 2954,1309 3000,1309 3052.5,1309 3101,1309 3151,1309 2617.5,1313.5 734,1342.5 856.21,1342.5 978.41,1342.5 1102,1342.5 1222.82,1342.5 1345.03,1342.5 1137,1408 1186.5,1408 1236,1408 2581,1441.5 734,1461.5 856.21,1461.5 978.41,1461.5 1345.03,1461.5 1102,1472.5 1272.5,1474.5 2581,1475.75 2581,1510 2003,1818 1999,1853.5 1887.5,1924 1930.5,1924 1845,1961.5 1718.5,1967.5 1798,1967.5 1882,2006 1915.5,2005.5 1719,2014 1798,2014 1139,2485.5 1196,2485.5 1253,2485.5 675.35,2553 797.56,2553 1041.97,2553 1164.18,2553 1286.38,2553 1408.59,2553 675.35,2657 797.56,2657 919.76,2657 1041.97,2657 1164.18,2657 1286.38,2657 1408.59,2657 1896.5,2659.18 1896.5,2748.79 675.35,2751.5 797.56,2751.5 919.76,2751.5 1041.97,2751.5 1164.18,2751.5 1286.38,2751.5 1408.59,2751.5 3344.47,2755.5 3466.68,2755.5 3588.88,2755.5 3711.09,2755.5 3833.29,2755.5 3955.5,2755.5 3344.47,2830.83 3466.68,2830.83 3588.88,2830.83 3711.09,2830.83 3833.29,2830.83 3955.5,2830.83 675.35,2837.5 797.56,2837.5 919.76,2837.5 1041.97,2837.5 1164.18,2837.5 1286.38,2837.5 1408.59,2837.5 1530.79,2837.5 1653,2837.5 1775.2,2837.5 1896.5,2837.5 3344.47,2906.17 3466.68,2906.17 3588.88,2906.17 3711.09,2906.17 3833.29,2906.17 3955.5,2906.17 675.35,2932 797.56,2932 919.76,2932 1041.97,2932 1164.18,2932 1286.38,2932 1408.59,2932 1530.79,2932 1653,2932 1775.2,2932 1896.5,2932 3344.47,2981.5 3466.68,2981.5 3588.88,2981.5 3711.09,2981.5 3833.29,2981.5 3955.5,2981.5
  other v2: 2770,1441 2816,1441 2862,1441 2908,1441 2954,1441 3000,1441 3051,1441 3097,1441 3143,1441 3193.5,1441 2770,1497 2816,1497 2862,1497 2908,1497 2954,1497 3000,1497 3051,1497 3097,1497 3143,1497 3193.5,1497 2146.5,2176.5 2188,2176.5 2249.5,2194.5 2319.55,2194.5 2389.59,2194.5 2459.64,2194.5 2529.68,2194.5 2599.73,2194.5 2669.77,2194.5 2739.82,2194.5 2809.86,2194.5 2879.91,2194.5 2949.95,2194.5 3020,2194.5 3182.42,2199.5 3213.5,2199.5 2146.5,2229 2188,2229 3182.42,2271.5 3213.5,2271.5
  other v3: 2191,1572.5 2218,1572.5 2366.5,1611.5 2501.5,1611.5 2634.5,1611.5 2768.5,1611.5 2902.5,1611.5 2308,1615
  other v5: 2131.5,2270
  other v7: 2212,1526.5
NetC9_2: C9.2 U1.8 | length 158.2
  Top Layer w10: C9.2@1991.5,2457.5 2014,2457.5 2029,2442.5 2029,2374.64 2028.91,2374.55 2028.91,2373.74 2028.91,2358.89 2040.46,2347.34 U1.8@2041,2347.34 ; U1.8@2040,2348 U1.8@2054,2348
NetC13_1: C13.1 R4.2 | length 111.2
  Top Layer w20: C13.1@1650,2652 1681.91,2652 R4.2@1738,2708.09
NetC15_2: C15.2 R6.2 | length 88.7
  Top Layer w12: C15.2@2219.33,2112.5 C15.2@2222.5,2112.5
  Top Layer w20: R6.2@2158.83,2052 C15.2@2219.33,2112.5
NetC24_1: C24.1 R9.1 | length 75.7
  Bottom Layer w20: C24.1@2262.5,1342.02 R9.1@2262.5,1417.68
NetC24_2: C24.2 R15.2 U3.2 | length 506.9
  Bottom Layer w20: C24.2@2325.5,1342.02 R15.2@2325.5,1270 2531,1270 2568,1307 2568,1388.5 2541.2,1415.3 U3.2@2483.54,1415.3
NetC25_2: C25.2 U2.8 | length 125.9
  Top Layer w10: C25.2@2000.5,1763.5 2028,1736 2028,1675 2039,1664 ; U2.8@2040.27,1663.53 U2.8@2050.74,1663.53
NetC29_1: C29.1 R12.2 | length 100.9
  Top Layer w10: C29.1@1651,1288.5 C29.1@1666.5,1288.5 ; R12.2@1736.5,1225.5 R12.2@1741,1230
  Top Layer w20: R12.2@1735.59,1233.5 R12.2@1738,1235.91
  Top Layer w30: C29.1@1666.5,1288.5 R12.2@1720,1235
NetC30_2: C30.2 R13.2 | length 91.1
  Top Layer w15: C30.2@2221.33,1422 C30.2@2224,1422
  Top Layer w20: R13.2@2158.83,1359.5 C30.2@2221.33,1422
NetR2_1: R2.1 R3.1 | length 152.7
  Top Layer w15: v6(2028.5,2020) 2028.5,2051 R3.1@2030,2052.5
  Top Layer w20: R2.1@2029,1898 v6@2029,1938
  Bottom Layer w15: v6@2028.5,1942.5 2029.5,1941.5 v6(2029,1941)
  Bottom Layer w20: v6@2028.5,1942.5 v6(2028.5,2020)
